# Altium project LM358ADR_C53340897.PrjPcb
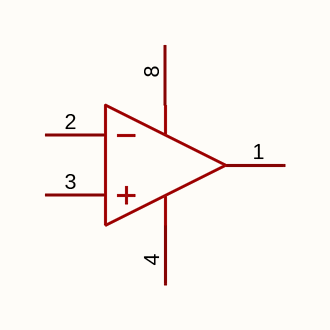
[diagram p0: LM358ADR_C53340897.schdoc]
1 sheet, 1 parts. Net scope: global (net labels, ports and power ports of the same name join across sheets).

## Sheet LM358ADR_C53340897.schdoc
size 127 x 101 mm

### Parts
U?  lm358adr(tp)  [SOIC-8_L5.0-W4.0-P1.27-LS6.0-BL]  (value not drawn)  (part A of 2)

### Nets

Not connected (* = marked no-connect by the designer): U? 1(OUT1) 2(IN1-) 3(IN1+) 4(VEE) 8(VCC)

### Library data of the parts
U? = lm358adr(tp): 放大器数:2;轨到轨:-;增益带宽积(GBW):1MHz;输入失调电压(Vos):2mV;压摆率(SR):400V/ms;输入偏置电流(Ib):50nA;; Manufacturer: TECH PUBLIC(台舟); Symbol: LM358ADR_C53340897; AddInBom: yes; ModelId: 7abc64c95a1a4a04a4ef38f9097c870b; ModelTransform: 192.913,236.22,0,0,0,0,0,0,0; Number of Channels: 2; Gain Bandwidth Product: 1MHz; Vos - Input Offset Voltage: 2mV; Ib - Input Bias Current: 50nA; Input Offset Current(Ios): 10nA; Common Mode Rejection Ratio(CMRR): 80dB; Quiescent Current: 500uA; Output Current: 40mA; Single supply: 3V~32V; Dual Supply: 1.5V~16V；-16V~-1.5V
